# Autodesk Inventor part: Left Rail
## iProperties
Shininess: 64.0
Length Units: 11272
Angle Units: 11279
Time Units: 11290
Mass Units: 11286
Length Display Precision: 3
Angle Display Precision: 2
Compacted: True
Part Number: Left Rail
Document SubType Name: Modeling
Created: 2003-10
Designer: jpittman
Manufacturer: Standard
Standards Organization: Custom
Density: 0.0
Volumn: 0.0
Area: 0.0
PropertySet Name: Model Information
Control State: 0
Master: False
Checked Out: False
Author: jpittman
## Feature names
1. Extrusion1
2. Extrusion2
3. Hole1
4. Extrusion3
5. Hole2
